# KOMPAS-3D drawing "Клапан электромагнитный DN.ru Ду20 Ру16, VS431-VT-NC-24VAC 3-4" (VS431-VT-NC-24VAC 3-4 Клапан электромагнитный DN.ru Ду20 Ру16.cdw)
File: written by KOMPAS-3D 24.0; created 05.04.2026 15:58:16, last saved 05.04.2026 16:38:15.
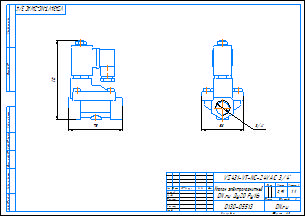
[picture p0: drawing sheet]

Document properties: c3d_UniqueCompID: ef56311e-7521-43dc-8291-0e6108b3d81d; Автор: artio; Класс точности: c; Знак неуказанной шероховатости: Шероховатость не задана; Рассекать на разрезах: Да; Автор: artio; Форматы листов документа: A3; Полное имя файла: VS431-VT-NC-24VAC 3-4 Клапан электромагнитный DN.ru Ду20 Ру16.m3d; Масса: 0.907; Наименование: Клапан электромагнитный DN.ru Ду20 Ру16; Количество листов документа: 1; Примечание: D130-05513

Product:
- Body: Тело 1  | qty 1
    Масса: 1.198355
- Part/product: Клапан электромагнитный DN.ru Ду20 Ру16  | designation VS431-VT-NC-24VAC 3-4
    Масса: 0.907
    Раздел спецификации: Прочие изделия
    Примечание: D130-05513
    additional columns: ef56311e-7521-43dc-8291-0e6108b3d81d; artio; c; Шероховатость не задана; Да

Views: Вид 1, Спереди, Проекционный вид 2
Referenced files in C:\Users\artio\OneDrive\Рабочий стол\Клапан электромагнитный DN.ru\VS431\VS431-ET-NC\: VS431-ET-NC-24VAC 3-4 Клапан электромагнитный DN.ru Ду20 Ру16.m3d
Referenced files in C:\Users\artio\OneDrive\Рабочий стол\Клапан электромагнитный DN.ru\VS431\VS431-VT-NC\: VS431-VT-NC-24VAC 3-4 Клапан электромагнитный DN.ru Ду20 Ру16.m3d
Referenced files in C:\Users\artio\OneDrive\Рабочий стол\Клапан электромагнитный DN.ru\VS431\VS431-NT-NC\: VS431-NT-NC-24VAC 3-4 Клапан электромагнитный DN.ru Ду20 Ру16.cdw
Referenced files in C:\Users\artio\OneDrive\Рабочий стол\Клапан электромагнитный DN.ru\VS431\VS431-VT-NC\VS431-VT-NC-24VAC\Ду20\: VS431-VT-NC-24VAC 3-4 Клапан электромагнитный DN.ru Ду20 Ру16.m3d
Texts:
  VS431-VT-NC-24VAC 3-4
  Клапан электромагнитный
  DN.ru Ду20 Ру16
  VS431-VT-NC-24VAC 3/4"
  VS431-VT-NC-24VAC 3/4"-
  Клапан электромагнитный DN.ru Ду20 Ру16
  VS431-VT-NC-24VAC 3-4 Клапан электромагнитный DN.ru Ду20 Ру16
Dimensions and other numbers on the sheet: 0; 3; 2; 4; 58; 3/4"; 75; 110; 1:1; 1; 0,91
